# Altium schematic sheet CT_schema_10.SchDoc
size 386 x 278 mm
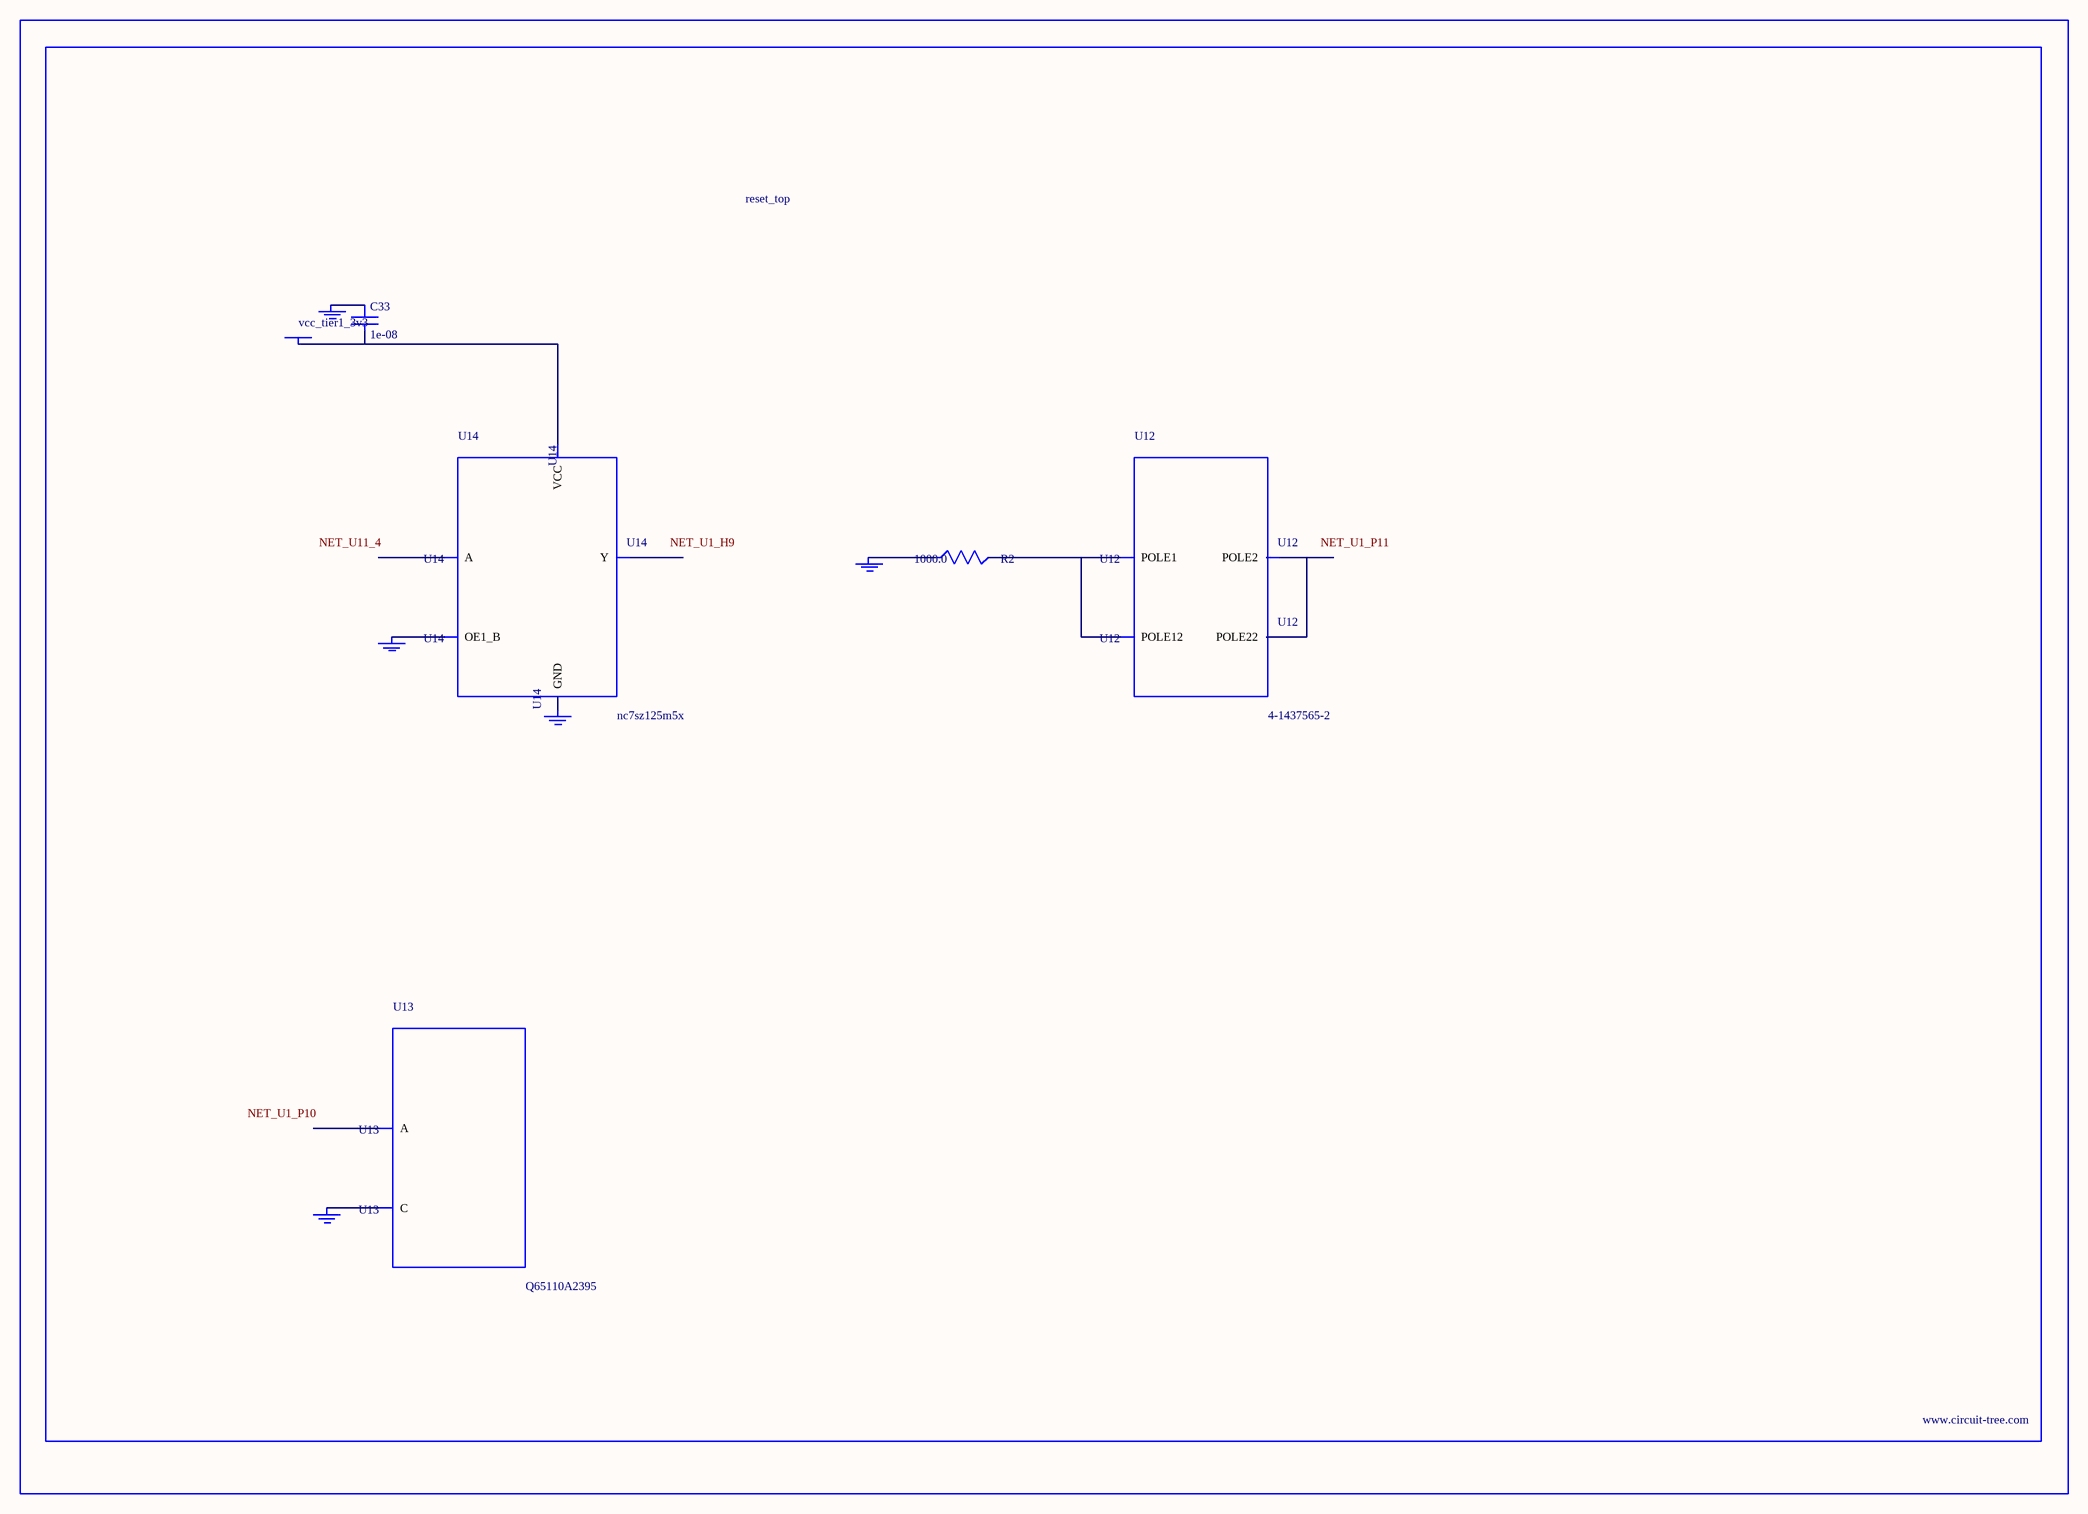
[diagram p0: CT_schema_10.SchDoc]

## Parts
BORDER9  (no value)
C33  1e-08  [C0402]
GND_INSTANCE_9_0  (no value)
GND_INSTANCE_9_1  (no value)
GND_INSTANCE_9_2  (no value)
GND_INSTANCE_9_3  (no value)
GND_INSTANCE_9_4  (no value)
POWER_INSTANCE_9_0  vcc_tier1_3v3
R2  1000.0  [R0603]
U12  4-1437565-2  [SW_4-1437565-2]
U13  Q65110A2395  [LGM67K-G1J2-24-Z]
U14  nc7sz125m5x  [NC7SZ125M5X]

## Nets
NetC33_1: C33.1 GND_INSTANCE_9_2.0(GND)
NetC33_2: C33.2 POWER_INSTANCE_9_0.0(PWR) U14.5(VCC)
NetGND_INSTANCE_9_0_0: GND_INSTANCE_9_0.0(GND) R2.1
NetGND_INSTANCE_9_1_0: GND_INSTANCE_9_1.0(GND) U13.C
NetGND_INSTANCE_9_3_0: GND_INSTANCE_9_3.0(GND) U14.1(OE1_B)
NetGND_INSTANCE_9_4_0: GND_INSTANCE_9_4.0(GND) U14.3(GND)
NetR2_2: R2.2 U12.1(POLE1) U12.2(POLE12)
NetU12_3: U12.3(POLE2) U12.4(POLE22)

Not connected (* = marked no-connect by the designer): U13 A; U14 2(A) 4(Y)

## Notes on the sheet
- Labels drawn without touching a wire or pin: NET_U1_H9, NET_U1_P10, NET_U1_P11, NET_U11_4

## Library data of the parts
BORDER9 = BORDER_PAGE9
C33 = C0402C103K3RAC
GND_INSTANCE_9_0-GND_INSTANCE_9_4 = GND
POWER_INSTANCE_9_0 = PWR
R2 = RC0603JR-071KL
